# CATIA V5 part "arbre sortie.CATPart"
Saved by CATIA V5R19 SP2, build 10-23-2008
Part number: arbre sortie
Publications: "diametre arbre sortie"
Bounding box of the stored display mesh (mm): x -120 to -68, y 5 to 15, z -4.99 to 4.99
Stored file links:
  C:\Users\Thinkmotion2\Desktop\Pack 1\IAO_2010_1396_fvigouroux\vigouroux\vigouroux\arbre sortie.CATPart
  C:\Users\Thinkmotion2\Desktop\Pack 1\IAO_2010_1396_fvigouroux\vigouroux\vigouroux\mecanisme IAO.CATProduct
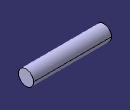
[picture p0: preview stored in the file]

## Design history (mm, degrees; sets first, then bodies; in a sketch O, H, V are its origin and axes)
Parameters
  `diametre arbre sortie` = 5 mm
Set1
  Plane1: linked copy from another document
  Point1: linked copy from another document
  Plane2: linked copy from another document
  Plane3: linked copy from another document
Body1 (main body)
  Sketch1 on Plane1, origin (-73, 0, 0), H (0, 1, 0), V (0, 0, 1)
    circle A1 centre (10, 0) radius 5
    point P1 (10, 0)
    reference projected point E1 (10, 0) from Point1
    radius A1 = 5 {= `diametre arbre sortie`}
    distance P1 E1 = 0
  Pad1: profile Sketch1, direction (-1, 0, 0), up to Plane2
  Pad2: profile Sketch1, direction (1, 0, 0), length 5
